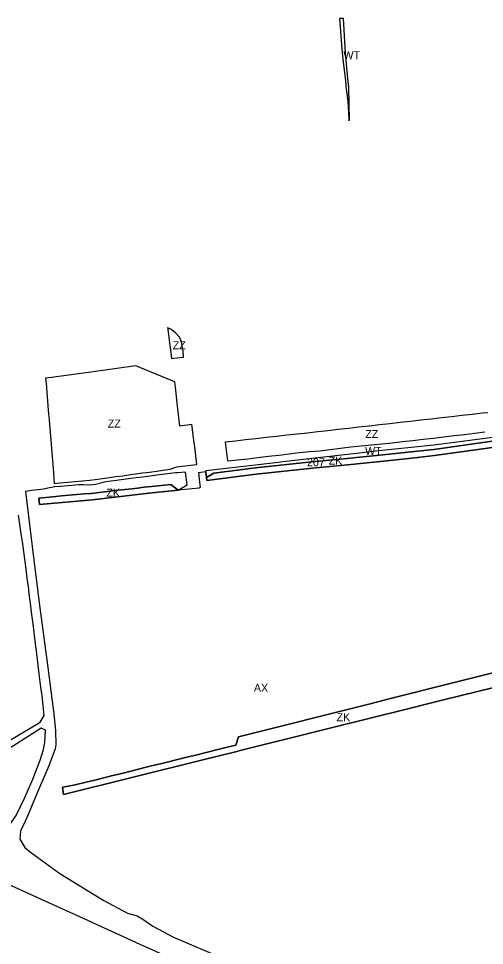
# Model space of a CAD drawing. Extents: x -521939 to -516426, y -1197857 to -1189551.
# Drawn here: x -519905 to -519323, y -1192859 to -1191700 of the extents above; entities that cross this region are included whole.
import ezdxf

# ---------------------------------------------------------------- set-up
doc = ezdxf.new("R2010")
doc.units = 0
for name, color, linetype in [('90640013', 7, 'Continuous'), ('90670013', 7, 'Continuous'), ('90710013', 7, 'Continuous'), ('90710023', 7, 'Continuous'), ('90760013', 7, 'Continuous'), ('ID_navrh', 7, 'Continuous')]:
    doc.layers.add(name, color=color, linetype=linetype)

msp = doc.modelspace()

# ---------------------------------------------------------------- linework, layer by layer
at = {"layer": '90640013'}
for points in [[(-519491.26, -1191827.06), (-519492.28, -1191786.23), (-519493.35, -1191774.96), (-519496.38, -1191742.87), (-519498.91, -1191700.04), (-519503.66, -1191700.1), (-519500.5, -1191743.31), (-519500.23, -1191746.39), (-519499.81, -1191751.23), (-519496.19, -1191777.33), (-519495.98, -1191784.43), (-519493.63, -1191803.43), (-519491.97, -1191825.26), (-519492.58, -1191827.06), (-519491.26, -1191827.06)], [(-519293.15, -1192221.23), (-519385.99, -1192233.14), (-519458.84, -1192240.98), (-519478.96, -1192243.26), (-519486.4, -1192244.11), (-519538.54, -1192250.02), (-519608.83, -1192258.36), (-519670.99, -1192265.56), (-519670.87, -1192266.69), (-519670.1, -1192273.68), (-519660.91, -1192268.23), (-519608.82, -1192261.75), (-519538.31, -1192254.24), (-519485.83, -1192249.1), (-519482.85, -1192248.8), (-519478.37, -1192248.37), (-519457.41, -1192246.31), (-519414.35, -1192241.81), (-519386.04, -1192238.58), (-519295.56, -1192225.98), (-519292.39, -1192228.11), (-519293.15, -1192221.23)]]:
    msp.add_lwpolyline(points, dxfattribs=at)
at = {"layer": '90670013'}
for points in [[(-519718.54, -1192088.87), (-519715.86, -1192108.31), (-519715.47, -1192111.43), (-519713.62, -1192125.09), (-519699.83, -1192123.44), (-519698.68, -1192123.2), (-519699.43, -1192115.26), (-519700.31, -1192109.31), (-519701.52, -1192103.24), (-519704.34, -1192097.82), (-519708.3, -1192093.18), (-519713.13, -1192089.43), (-519715.18, -1192088.33), (-519718.49, -1192086.54), (-519718.88, -1192086.43), (-519718.54, -1192088.87)], [(-519860.38, -1192281.16), (-519853.37, -1192280.53), (-519834.23, -1192278.75), (-519824.87, -1192277.87), (-519816.11, -1192277.01), (-519809.24, -1192276.09), (-519802.82, -1192275.23), (-519791.27, -1192273.73), (-519783.18, -1192272.68), (-519774.6, -1192271.54), (-519767.15, -1192270.44), (-519765.04, -1192270.13), (-519758.67, -1192269.29), (-519750.1, -1192268.09), (-519741.32, -1192266.86), (-519732.71, -1192265.72), (-519724.3, -1192264.56), (-519715.34, -1192263.41), (-519706.96, -1192260.59), (-519697.08, -1192259.23), (-519681.98, -1192257.35), (-519684.65, -1192235.35), (-519685.37, -1192230.59), (-519688.26, -1192207.37), (-519703.26, -1192209.36), (-519706.98, -1192177.01), (-519708.47, -1192164.31), (-519709.78, -1192154.13), (-519734.11, -1192144.17), (-519758.43, -1192134.21), (-519814.81, -1192141.93), (-519863.67, -1192148.61), (-519871.18, -1192149.64), (-519870.61, -1192155.68), (-519867.87, -1192189.47), (-519866.84, -1192202.11), (-519861.47, -1192267.81), (-519860.38, -1192281.16)], [(-519318.4, -1192192.73), (-519324.93, -1192193.46), (-519337.87, -1192194.92), (-519350.84, -1192196.38), (-519363.6, -1192197.82), (-519376.32, -1192199.25), (-519389.29, -1192200.71), (-519402.15, -1192202.16), (-519415, -1192203.61), (-519427.82, -1192205.05), (-519440.9, -1192206.52), (-519453.68, -1192207.96), (-519466.6, -1192209.41), (-519479.61, -1192210.87), (-519492.35, -1192212.31), (-519505.42, -1192213.78), (-519518.29, -1192215.23), (-519531.06, -1192216.67), (-519543.92, -1192218.12), (-519556.92, -1192219.58), (-519569.58, -1192221.01), (-519582.48, -1192222.46), (-519595.48, -1192223.92), (-519608.45, -1192225.38), (-519621.19, -1192226.81), (-519633.87, -1192228.24), (-519646.69, -1192229.68), (-519643.97, -1192252.95), (-519631.14, -1192251.45), (-519618.48, -1192250.28), (-519605.74, -1192248.7), (-519592.74, -1192247.02), (-519579.82, -1192245.81), (-519566.88, -1192244.15), (-519554.2, -1192242.66), (-519541.4, -1192241.29), (-519528.34, -1192240.22), (-519515.54, -1192238.85), (-519502.68, -1192237.21), (-519489.62, -1192235.55), (-519476.84, -1192234.28), (-519463.7, -1192232.94), (-519450.83, -1192231.68), (-519438.08, -1192230.21), (-519425.05, -1192228.82), (-519412.12, -1192227.34), (-519399.25, -1192225.86), (-519386.39, -1192224.39), (-519373.52, -1192222.91), (-519360.66, -1192221.43), (-519347.79, -1192219.96), (-519334.91, -1192218.48), (-519322.01, -1192216.62)]]:
    msp.add_lwpolyline(points, dxfattribs=at)
at = {"layer": '90710013'}
for points in [[(-519705.65, -1192289.69), (-519705.67, -1192289.48), (-519714.7, -1192282.4), (-519730.36, -1192284.05), (-519738.89, -1192284.99), (-519747.79, -1192285.95), (-519756.5, -1192286.97), (-519762.85, -1192287.7), (-519772.27, -1192288.77), (-519780.91, -1192289.74), (-519790.95, -1192290.91), (-519807.52, -1192292.86), (-519814.16, -1192293.61), (-519822.9, -1192294.34), (-519832.38, -1192295.12), (-519851.37, -1192296.72), (-519858.25, -1192297.38), (-519866.74, -1192298.17), (-519879.64, -1192299.39), (-519878.88, -1192307.35), (-519812.44, -1192301.5), (-519742.17, -1192293.39), (-519705.65, -1192289.69)], [(-519271.05, -1192507.61), (-519443.57, -1192550.97), (-519444.23, -1192551.14), (-519445.03, -1192551.34), (-519448.11, -1192552.11), (-519465.49, -1192556.48), (-519630.06, -1192597.85), (-519633.56, -1192608.18), (-519647.57, -1192611.7), (-519657.37, -1192614.13), (-519681.85, -1192620.25), (-519694.74, -1192623.42), (-519709.73, -1192627.17), (-519717.73, -1192629.13), (-519725.94, -1192631.17), (-519738.69, -1192634.33), (-519747.21, -1192636.42), (-519754.9, -1192638.35), (-519770.8, -1192642.27), (-519779.66, -1192644.53), (-519788.96, -1192646.84), (-519809.53, -1192651.89), (-519820.29, -1192654.59), (-519834.11, -1192657.91), (-519844.86, -1192660.14), (-519850.15, -1192660.66), (-519848.77, -1192670.05), (-519674.6, -1192626.61), (-519632.14, -1192616.02), (-519628.19, -1192615.14), (-519443.92, -1192569.11), (-519440.02, -1192568.15), (-519372.23, -1192551.03), (-519253.11, -1192522.25)]]:
    msp.add_lwpolyline(points, dxfattribs=at)
at = {"layer": '90710023'}
msp.add_lwpolyline([(-519670.1, -1192273.68), (-519669.7, -1192277.39), (-519607.9, -1192269.69), (-519537.49, -1192262.2), (-519484.92, -1192257.05), (-519481.94, -1192256.7), (-519477.47, -1192256.17), (-519456.62, -1192254.15), (-519413.5, -1192249.64), (-519385.05, -1192246.39), (-519291.8, -1192233.4), (-519292.39, -1192228.11), (-519295.56, -1192225.98), (-519386.04, -1192238.58), (-519414.35, -1192241.81), (-519457.41, -1192246.31), (-519478.37, -1192248.37), (-519482.85, -1192248.8), (-519485.83, -1192249.1), (-519538.31, -1192254.24), (-519608.82, -1192261.75), (-519660.91, -1192268.23), (-519670.1, -1192273.68)], dxfattribs=at)
at = {"layer": '90760013'}
for points in [[(-519291.8, -1192233.4), (-519385.05, -1192246.39), (-519413.5, -1192249.64), (-519456.62, -1192254.15), (-519477.47, -1192256.17), (-519481.94, -1192256.7), (-519484.92, -1192257.05), (-519537.49, -1192262.2), (-519607.9, -1192269.69), (-519669.7, -1192277.39), (-519670.1, -1192273.68)], [(-519670.1, -1192273.68), (-519670.87, -1192266.69), (-519680.1, -1192268.07), (-519678.64, -1192279.67), (-519677.99, -1192286.33), (-519679.44, -1192287.03), (-519705.65, -1192289.69), (-519742.17, -1192293.39), (-519812.44, -1192301.5), (-519878.88, -1192307.35), (-519879.64, -1192299.39), (-519866.74, -1192298.17), (-519858.25, -1192297.38), (-519851.37, -1192296.72), (-519832.38, -1192295.12), (-519822.9, -1192294.34), (-519814.16, -1192293.61), (-519807.52, -1192292.86), (-519790.95, -1192290.91), (-519780.91, -1192289.74), (-519772.27, -1192288.77), (-519762.85, -1192287.7), (-519756.5, -1192286.97), (-519747.79, -1192285.95), (-519738.89, -1192284.99), (-519730.36, -1192284.05), (-519714.7, -1192282.4), (-519705.67, -1192289.48), (-519703.27, -1192288.12), (-519694.21, -1192282.82), (-519696.13, -1192267), (-519705.99, -1192267.85), (-519708.66, -1192268.04), (-519732.03, -1192270.99), (-519740.62, -1192272.07), (-519749.43, -1192273.18), (-519758.03, -1192274.28), (-519764.52, -1192275.08), (-519773.99, -1192276.27), (-519782.57, -1192277.38), (-519792.59, -1192278.63), (-519795.72, -1192279.01), (-519808.94, -1192282.39), (-519815.36, -1192283.3), (-519824.22, -1192283.09), (-519830.01, -1192283), (-519833.86, -1192283.34), (-519852.82, -1192284.97), (-519859.77, -1192285.53), (-519861.73, -1192285.73), (-519868.32, -1192287.24), (-519873.68, -1192288.51), (-519880.63, -1192289.15), (-519888.95, -1192289.92), (-519896.33, -1192291.31), (-519887.75, -1192359.93), (-519879.01, -1192430.53), (-519868.46, -1192511.25), (-519864.74, -1192540.33), (-519861, -1192569.32), (-519858.8, -1192590.58), (-519858.51, -1192607.7), (-519859.02, -1192613.05), (-519866.95, -1192634.05), (-519883.59, -1192673.01), (-519893.83, -1192697.06), (-519899.04, -1192708.67), (-519902.42, -1192715.87), (-519903.22, -1192725.88), (-519897, -1192736.11), (-519889.94, -1192741.9), (-519853.29, -1192768.82), (-519798.31, -1192802.61), (-519768.91, -1192818.48), (-519756.9, -1192821.72), (-519749.68, -1192825.91), (-519736.95, -1192834.43), (-519711.44, -1192848.38), (-519646.77, -1192875.82)], [(-519872.8, -1192571.21), (-519874.18, -1192558.92), (-519875.66, -1192546.69), (-519876.95, -1192535.97), (-519878.19, -1192525.73), (-519879, -1192519.17), (-519881.65, -1192497.64), (-519882.55, -1192490.66), (-519883.69, -1192481.55), (-519884.97, -1192471.33), (-519886.39, -1192459.97), (-519887.51, -1192450.99), (-519888.69, -1192441.94), (-519890.02, -1192430.9), (-519891.14, -1192422.37), (-519892.69, -1192410.59), (-519894.12, -1192399.59), (-519895.56, -1192388.49), (-519900.24, -1192353.9), (-519901.65, -1192344.58), (-519903.52, -1192332.49), (-519905.16, -1192320.75)], [(-519253.11, -1192522.25), (-519372.23, -1192551.03), (-519440.02, -1192568.15), (-519443.92, -1192569.11), (-519628.19, -1192615.14), (-519632.14, -1192616.02), (-519674.6, -1192626.61), (-519848.77, -1192670.05), (-519850.15, -1192660.66), (-519844.86, -1192660.14), (-519834.11, -1192657.91), (-519820.29, -1192654.59), (-519809.53, -1192651.89), (-519788.96, -1192646.84), (-519779.66, -1192644.53), (-519770.8, -1192642.27), (-519754.9, -1192638.35), (-519747.21, -1192636.42), (-519738.69, -1192634.33), (-519725.94, -1192631.17), (-519717.73, -1192629.13), (-519709.73, -1192627.17), (-519694.74, -1192623.42), (-519681.85, -1192620.25), (-519657.37, -1192614.13), (-519647.57, -1192611.7), (-519633.56, -1192608.18), (-519630.06, -1192597.85), (-519465.49, -1192556.48), (-519448.11, -1192552.11), (-519445.03, -1192551.34), (-519444.23, -1192551.14), (-519443.57, -1192550.97), (-519271.05, -1192507.61)], [(-519946.53, -1192620.31), (-519878.04, -1192579.76), (-519872.8, -1192571.21)], [(-519973.13, -1192671.04), (-519945.35, -1192695.43), (-519928.14, -1192710.54), (-519920.96, -1192711.64), (-519915.4, -1192706.96), (-519907.96, -1192696.03), (-519907.66, -1192695.43), (-519897.61, -1192674.42), (-519889.55, -1192656.44), (-519887.28, -1192650.8), (-519877.84, -1192627.03), (-519873.78, -1192613.72), (-519872.16, -1192604.77), (-519871.43, -1192589.64), (-519876.72, -1192586.93), (-519926.45, -1192618.64), (-519939.66, -1192630.65), (-519948.49, -1192642.24), (-519965.83, -1192662.43), (-519973.13, -1192671.04)], [(-519717.76, -1192873.41), (-519752.94, -1192857.37), (-519788.21, -1192841.3), (-519805.68, -1192833.36), (-519819.07, -1192827.26), (-519848.77, -1192813.79), (-519927.45, -1192777.89), (-519929.51, -1192777.57), (-519938.48, -1192797.62), (-519941.05, -1192804.31), (-519950.26, -1192821.29), (-519960.56, -1192843.19), (-519966.94, -1192857.93), (-519970.35, -1192865.66)]]:
    msp.add_lwpolyline(points, dxfattribs=at)

# ---------------------------------------------------------------- texts
at = {"layer": '90640013'}
for rotation, p in [(360, (-519498.98, -1191750.93)), (0, (-519471.87, -1192245.5))]:
    msp.add_text('WT', height=10, rotation=rotation, dxfattribs=at).set_placement(p)
at = {"layer": '90670013'}
for rotation, p in [(360, (-519712.31, -1192113.43)), (0, (-519793.51, -1192211.35)), (0, (-519471.69, -1192224.42))]:
    msp.add_text('ZZ', height=10, rotation=rotation, dxfattribs=at).set_placement(p)
at = {"layer": '90710013'}
for rotation, p in [(0, (-519795.31, -1192297.73)), (360, (-519507.65, -1192578.39))]:
    msp.add_text('ZK', height=10, rotation=rotation, dxfattribs=at).set_placement(p)
at = {"layer": '90710023'}
msp.add_text('ZK', height=10, rotation=360, dxfattribs=at).set_placement((-519517.41, -1192257.73))
at = {"layer": '90760013'}
msp.add_text('AX', height=10, rotation=360, dxfattribs=at).set_placement((-519610.86, -1192541.59))
at = {"layer": 'ID_navrh'}
msp.add_text('207', height=10, rotation=360, dxfattribs=at).set_placement((-519544.49, -1192259.73))

doc.saveas('drawing.dxf')
